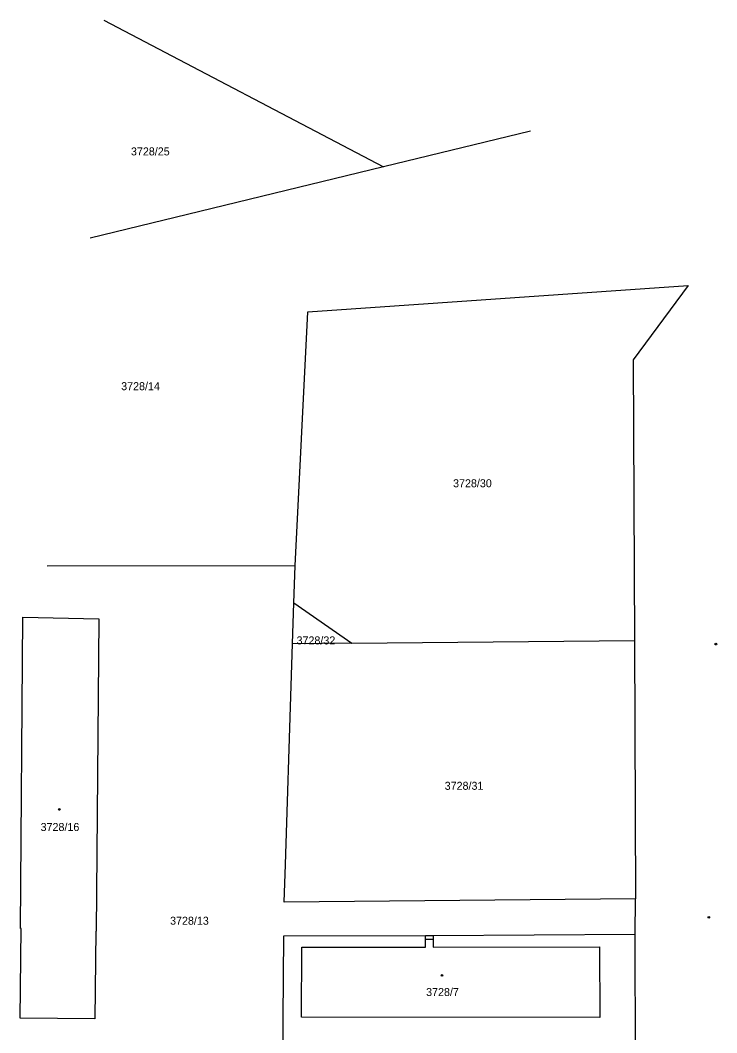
# Model space of a CAD drawing. Extents: x -527335 to -526256, y -1079142 to -1077836.
# Drawn here: x -526509.1 to -526361.2, y -1078183.4 to -1077968.4 of the extents above; entities that cross this region are included whole.
import ezdxf

# ---------------------------------------------------------------- set-up
doc = ezdxf.new("R2010")
doc.units = 0
for name, color, linetype in [('Hranice parcel', 7, 'Continuous'), ('Parcelní čísla', 7, 'Continuous'), ('Vnitřní kresba', 7, 'Continuous'), ('Značky budov', 7, 'Continuous')]:
    doc.layers.add(name, color=color, linetype=linetype)

msp = doc.modelspace()

# ---------------------------------------------------------------- linework, layer by layer
at = {"layer": 'Hranice parcel'}
for p, q in [((-526491.37, -1077968.39), (-526431.97, -1077999.5)), ((-526400.75, -1077991.92), (-526431.97, -1077999.5)), ((-526431.97, -1077999.5), (-526494.24, -1078014.63)), ((-526450.76, -1078084.21), (-526503.4, -1078084.27)), ((-526451.02, -1078092.08), (-526450.76, -1078084.21)), ((-526451.3, -1078100.77), (-526451.02, -1078092.08)), ((-526451.02, -1078092.08), (-526438.72, -1078100.65)), ((-526438.72, -1078100.65), (-526378.72, -1078100.08)), ((-526378.72, -1078100.08), (-526378.46, -1078154.92)), ((-526438.72, -1078100.65), (-526451.3, -1078100.77)), ((-526378.56, -1078162.53), (-526378.46, -1078154.92)), ((-526378.56, -1078162.53), (-526421.44, -1078162.78)), ((-526421.44, -1078162.78), (-526423.04, -1078162.78))]:
    msp.add_line(p, q, dxfattribs=at)
for points in [[(-526450.76, -1078084.21), (-526448.05, -1078030.31), (-526367.31, -1078024.69)], [(-526367.31, -1078024.69), (-526379.01, -1078040.47), (-526378.72, -1078100.08)], [(-526508.9, -1078161.24), (-526509.01, -1078161.24), (-526508.5, -1078095.15), (-526492.37, -1078095.48), (-526492.95, -1078161.84), (-526493.06, -1078161.83), (-526493.24, -1078180.39), (-526509.08, -1078180.27), (-526508.9, -1078161.24)], [(-526378.46, -1078154.92), (-526453.05, -1078155.62), (-526452.8, -1078147.63), (-526451.59, -1078109.7), (-526451.3, -1078100.77)], [(-526378.41, -1078205.39), (-526378.43, -1078198.99), (-526378.47, -1078188.81), (-526378.56, -1078162.53)], [(-526423.04, -1078162.78), (-526453.19, -1078162.9), (-526453.32, -1078180.38), (-526453.46, -1078202.22), (-526450.43, -1078205.28), (-526426.47, -1078205.32)], [(-526421.44, -1078162.78), (-526421.44, -1078163.53), (-526421.44, -1078165.18), (-526386.1, -1078165.13), (-526386.04, -1078180.17), (-526449.36, -1078180.08), (-526449.34, -1078165.22), (-526423.04, -1078165.18), (-526423.04, -1078163.53), (-526423.04, -1078162.78)]]:
    msp.add_lwpolyline(points, dxfattribs=at)
at = {"layer": 'Vnitřní kresba'}
msp.add_line((-526423.04, -1078163.53), (-526421.44, -1078163.53), dxfattribs=at)
at = {"layer": 'Značky budov'}
for centre in [(-526361.42, -1078100.86), (-526500.79, -1078135.96), (-526362.92, -1078158.86), (-526419.55, -1078171.21)]:
    msp.add_circle(centre, 0.175, dxfattribs=at)

# ---------------------------------------------------------------- texts
at = {"layer": 'Parcelní čísla'}
for s, p in [('3728/25', (-526485.58, -1077997.09)), ('3728/14', (-526487.66, -1078046.94)), ('3728/30', (-526417.21, -1078067.55)), ('3728/32', (-526450.43, -1078100.92)), ('3728/31', (-526418.99, -1078131.79)), ('3728/16', (-526504.76, -1078140.54)), ('3728/13', (-526477.28, -1078160.44)), ('3728/7', (-526422.93, -1078175.58))]:
    msp.add_text(s, height=1.7, dxfattribs=at).set_placement(p)

doc.saveas('drawing.dxf')
